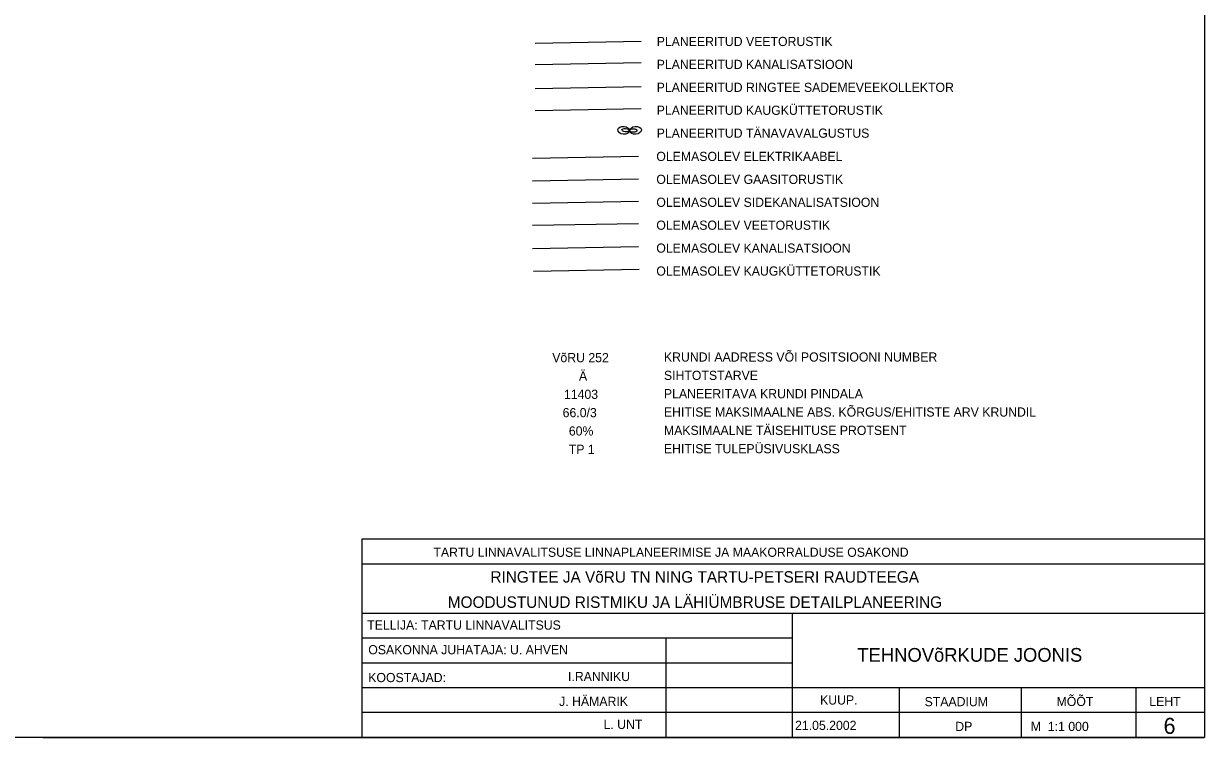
# Model space of a CAD drawing. Extents: x 9156 to 9809, y 2728 to 4000.
# Drawn here: x 9544.2 to 9801.6, y 3329.6 to 3485.3 of the extents above; entities that cross this region are included whole.
import ezdxf

# ---------------------------------------------------------------- set-up
doc = ezdxf.new("R2010")
doc.units = 0
for name, color, linetype in [('Level 61', 7, 'Continuous'), ('Level 63', 7, 'Continuous'), ('Level 8', 7, 'Continuous')]:
    doc.layers.add(name, color=color, linetype=linetype)

msp = doc.modelspace()

# ---------------------------------------------------------------- linework, layer by layer
at = {"layer": 'Level 61'}
for p, q in [((9655.75, 3481.08), (9678.83, 3481.5)), ((9655.75, 3476.39), (9678.83, 3476.81)), ((9655.75, 3471.16), (9678.83, 3471.58)), ((9655.75, 3466.38), (9678.83, 3466.8)), ((9655.16, 3455.97), (9678.24, 3456.39)), ((9655.16, 3451.05), (9678.24, 3451.47)), ((9655.16, 3446.13), (9678.24, 3446.56)), ((9655.16, 3441.33), (9678.24, 3441.75)), ((9655.16, 3436.28), (9678.24, 3436.71)), ((9655.34, 3431.32), (9678.42, 3431.74))]:
    msp.add_line(p, q, dxfattribs=at)
at = {"layer": 'Level 63'}
for p, q in [((9617.93, 3372.85), (9617.93, 3329.64)), ((9711.76, 3356.65), (9711.76, 3329.64)), ((9684.21, 3351.25), (9684.21, 3329.64)), ((9735.1, 3340.45), (9735.1, 3329.64)), ((9761.7, 3340.45), (9761.7, 3329.64)), ((9786.68, 3340.45), (9786.68, 3329.64)), ((9548.46, 3329.64), (9801.62, 3329.64))]:
    msp.add_line(p, q, dxfattribs=at)
msp.add_lwpolyline([(9275.53, 3966.8), (9801.62, 3966.8), (9801.62, 3329.64), (9275.53, 3329.64)], close=True, dxfattribs=at)
for points in [[(9801.62, 3372.85), (9617.93, 3372.85)], [(9801.62, 3367.45), (9617.93, 3367.45)], [(9801.62, 3356.65), (9617.93, 3356.65)], [(9711.76, 3351.25), (9617.93, 3351.25)], [(9711.76, 3345.85), (9617.93, 3345.85)], [(9801.62, 3340.45), (9617.93, 3340.45)], [(9801.62, 3335.05), (9617.93, 3335.05)]]:
    msp.add_lwpolyline(points, dxfattribs=at)
at = {"layer": 'Level 8'}
for centre, major_axis, ratio in [((9675, 3462.04), (1.28, -0.15), 0.674652), ((9675, 3462.04), (1.28, -0.15), 0.674652), ((9675, 3462.04), (1.28, -0.15), 0.674652), ((9675, 3462.04), (1.28, -0.15), 0.674652), ((9675.4, 3462.08), (0.774, -0.072), 0.486914), ((9675.4, 3462.08), (0.774, -0.072), 0.486914), ((9675.4, 3462.08), (0.774, -0.072), 0.486914), ((9675.4, 3462.08), (0.774, -0.072), 0.486914), ((9677.59, 3462.04), (-1.28, -0.15), 0.674652), ((9677.59, 3462.04), (-1.28, -0.15), 0.674652), ((9677.59, 3462.04), (-1.28, -0.15), 0.674652), ((9677.59, 3462.04), (-1.28, -0.15), 0.674652), ((9677.13, 3462), (-0.778, 0.002), 0.486914), ((9677.13, 3462), (-0.778, 0.002), 0.486914), ((9677.13, 3462), (-0.778, 0.002), 0.486914), ((9677.13, 3462), (-0.778, 0.002), 0.486914)]:
    msp.add_ellipse(centre, major_axis=major_axis, ratio=ratio, dxfattribs=at)

# ---------------------------------------------------------------- texts
at = {"layer": 'Level 61'}
for s, p in [('PLANEERITUD VEETORUSTIK', (9682.21, 3480.42)), ('PLANEERITUD KANALISATSIOON', (9682.21, 3475.42)), ('PLANEERITUD RINGTEE SADEMEVEEKOLLEKTOR', (9682.21, 3470.42)), ('PLANEERITUD KAUGKÜTTETORUSTIK', (9682.21, 3465.42)), ('PLANEERITUD TÄNAVAVALGUSTUS', (9682.21, 3460.42)), ('OLEMASOLEV ELEKTRIKAABEL', (9682.13, 3455.35)), ('OLEMASOLEV GAASITORUSTIK', (9682.13, 3450.35)), ('OLEMASOLEV SIDEKANALISATSIOON', (9682.13, 3445.35)), ('OLEMASOLEV VEETORUSTIK', (9682.13, 3440.35)), ('OLEMASOLEV KANALISATSIOON', (9682.13, 3435.35)), ('OLEMASOLEV KAUGKÜTTETORUSTIK', (9682.13, 3430.35)), ('VõRU 252', (9659.44, 3411.47)), ('KRUNDI AADRESS VÕI POSITSIOONI NUMBER', (9683.79, 3411.6)), ('Ä', (9665.27, 3407.47)), ('SIHTOTSTARVE', (9683.79, 3407.6)), ('11403', (9662, 3403.47)), ('PLANEERITAVA KRUNDI PINDALA', (9683.79, 3403.6)), ('66.0/3', (9661.71, 3399.47)), ('EHITISE MAKSIMAALNE ABS. KÕRGUS/EHITISTE ARV KRUNDIL', (9683.79, 3399.6)), ('MAKSIMAALNE TÄISEHITUSE PROTSENT', (9683.79, 3395.6)), ('60%', (9663.06, 3395.47)), ('TP 1', (9663.05, 3391.47)), ('EHITISE TULEPÜSIVUSKLASS', (9683.79, 3391.6))]:
    msp.add_text(s, height=2, dxfattribs=at).set_placement(p)
at = {"layer": 'Level 63'}
for s, height, p in [('TARTU LINNAVALITSUSE LINNAPLANEERIMISE JA MAAKORRALDUSE OSAKOND', 2, (9633.54, 3369.02)), ('RINGTEE JA VõRU TN NING TARTU-PETSERI RAUDTEEGA', 2.5, (9645.97, 3363.39)), ('MOODUSTUNUD RISTMIKU JA LÄHIÜMBRUSE DETAILPLANEERING', 2.5, (9636.68, 3357.89)), ('TELLIJA: TARTU LINNAVALITSUS', 2, (9619.1, 3353.14)), ('OSAKONNA JUHATAJA: U. AHVEN', 2, (9619.33, 3347.76)), ('TEHNOVõRKUDE JOONIS', 3, (9725.96, 3346.13)), ('KOOSTAJAD:', 2, (9619.33, 3341.69)), ('I.RANNIKU', 2, (9662.88, 3341.92)), ('J. HÄMARIK', 2, (9660.94, 3336.49)), ('KUUP.', 2, (9717.83, 3336.8)), ('MÕÕT', 2, (9769.39, 3336.48)), ('STAADIUM', 2, (9740.62, 3336.44)), ('LEHT', 2, (9789.61, 3336.48)), ('6', 3.5, (9792.72, 3330.4)), ('L. UNT', 2, (9670.62, 3331.48)), ('21.05.2002', 2, (9712.38, 3331.26)), ('DP', 2, (9747.31, 3331.03)), ('M  1:1 000', 2, (9763.77, 3331.03))]:
    msp.add_text(s, height=height, dxfattribs=at).set_placement(p)

doc.saveas('drawing.dxf')
